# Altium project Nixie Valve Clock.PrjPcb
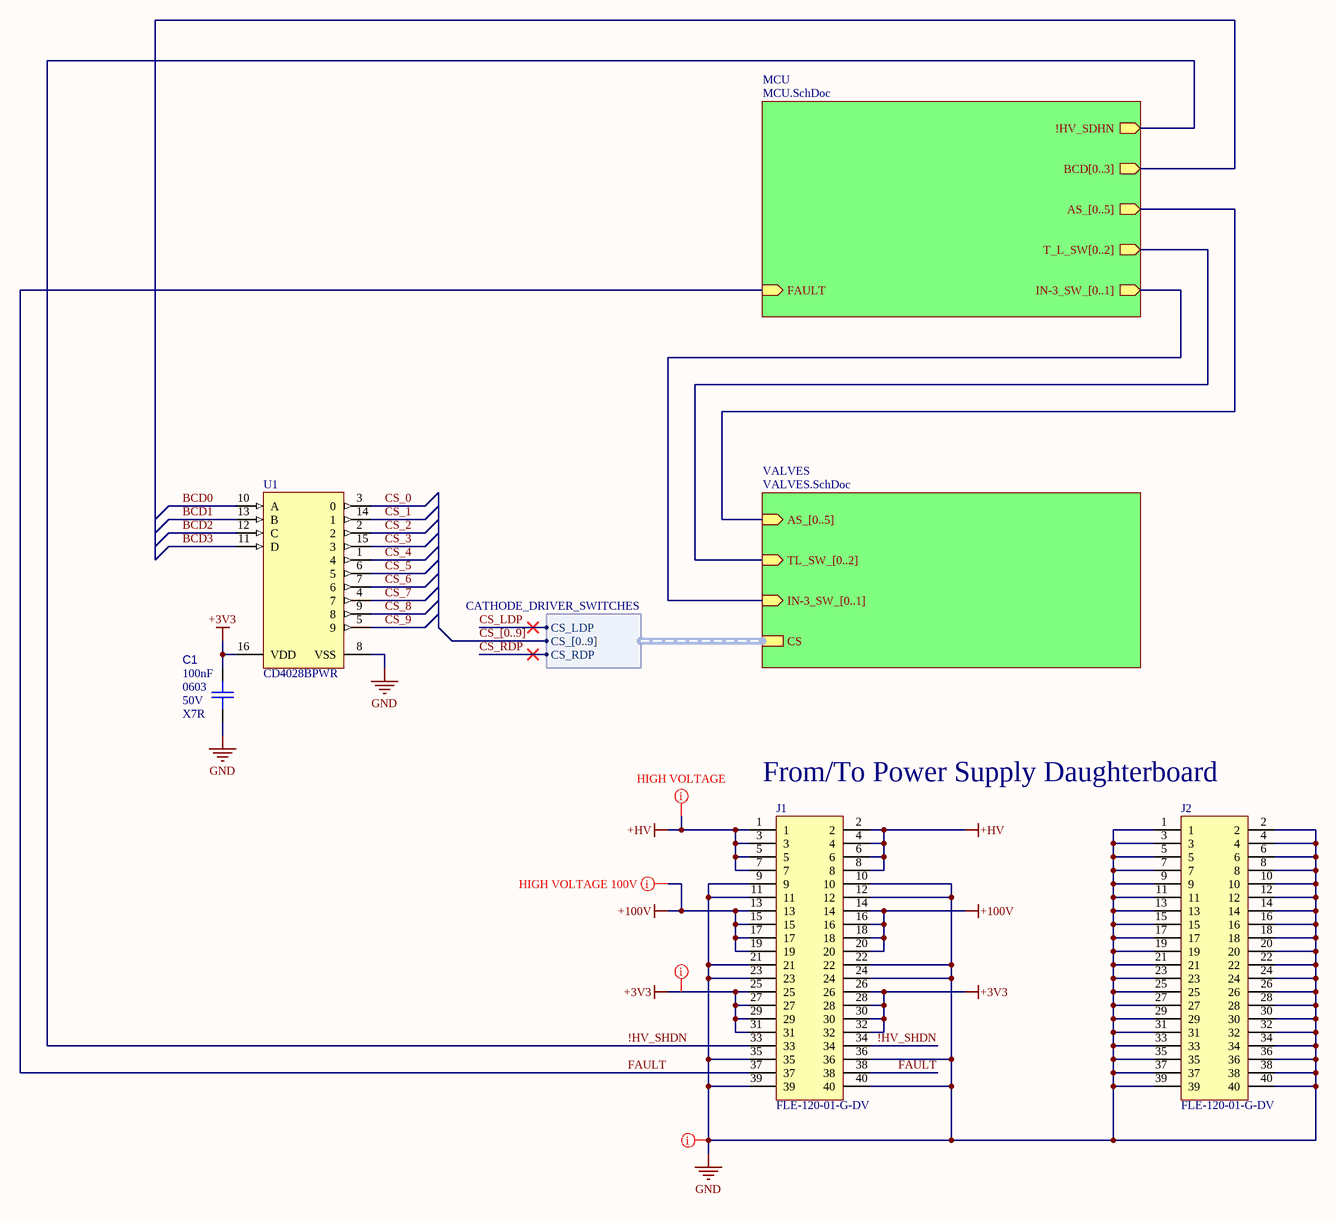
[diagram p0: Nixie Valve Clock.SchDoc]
9 sheets, 163 parts. Net scope: hierarchical (ports join the sheet entries above them; power ports are global).
Board file: Nixie Valve Clock.PcbDoc
Sheets:
  Nixie Valve Clock.SchDoc
    MCU = MCU.SchDoc
    VALVES = VALVES.SchDoc
      IN-14 VALVE ANODE DRIVER0 = IN-14 VALVE ANODE DRIVER.SchDoc
      IN-14 VALVE ANODE DRIVER1 = IN-14 VALVE ANODE DRIVER.SchDoc
      IN-14 VALVE ANODE DRIVER2 = IN-14 VALVE ANODE DRIVER.SchDoc
      IN-14 VALVE ANODE DRIVER3 = IN-14 VALVE ANODE DRIVER.SchDoc
      IN-14 VALVE ANODE DRIVER4 = IN-14 VALVE ANODE DRIVER.SchDoc
      IN-14 VALVE ANODE DRIVER5 = IN-14 VALVE ANODE DRIVER.SchDoc
      IN-14 VALVE CATHODE DRIVER_0 = IN-14 VALVE CATHODE DRIVER.SchDoc
      IN-14 VALVE CATHODE DRIVER_1 = IN-14 VALVE CATHODE DRIVER.SchDoc
      IN-14 VALVE CATHODE DRIVER_2 = IN-14 VALVE CATHODE DRIVER.SchDoc
      IN-14 VALVE CATHODE DRIVER_3 = IN-14 VALVE CATHODE DRIVER.SchDoc
      IN-14 VALVE CATHODE DRIVER_4 = IN-14 VALVE CATHODE DRIVER.SchDoc
      IN-14 VALVE CATHODE DRIVER_5 = IN-14 VALVE CATHODE DRIVER.SchDoc
      IN-14 VALVE CATHODE DRIVER_6 = IN-14 VALVE CATHODE DRIVER.SchDoc
      IN-14 VALVE CATHODE DRIVER_7 = IN-14 VALVE CATHODE DRIVER.SchDoc
      IN-14 VALVE CATHODE DRIVER_8 = IN-14 VALVE CATHODE DRIVER.SchDoc
      IN-14 VALVE CATHODE DRIVER_9 = IN-14 VALVE CATHODE DRIVER.SchDoc
      IN-14_VALVE_x2_0 = IN-14 VALVE x2.SchDoc
        IN-14 VALVE_0 = IN-14 VALVE.SchDoc
        IN-14 VALVE_1 = IN-14 VALVE.SchDoc
      IN-14_VALVE_x2_1 = IN-14 VALVE x2.SchDoc
        IN-14 VALVE_0 = IN-14 VALVE.SchDoc
        IN-14 VALVE_1 = IN-14 VALVE.SchDoc
      IN-14_VALVE_x2_2 = IN-14 VALVE x2.SchDoc
        IN-14 VALVE_0 = IN-14 VALVE.SchDoc
        IN-14 VALVE_1 = IN-14 VALVE.SchDoc
      IN-3 VALVE_0 = IN-3 VALVE.SchDoc
      IN-3 VALVE_1 = IN-3 VALVE.SchDoc
      IN-3 VALVE CATHODE DRIVER0 = IN-3 VALVE CATHODE DRIVER.SchDoc
      IN-3 VALVE CATHODE DRIVER1 = IN-3 VALVE CATHODE DRIVER.SchDoc

## Sheet Nixie Valve Clock.SchDoc
size A3; SheetNumber: 1; SheetTotal: 9

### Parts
(Parts that share a designator on the sheet are numbered #1, #2 ... from top to bottom, then left to right.)
?#1  (no value)
C1  value 100nF  Voltage Rating: 50V  Case/Package: 0603  Dielectric: X7R  [CAPC1608X09N]  (hidden comment: CGA3E2X7R1H104K080AA)
J1  FLE-120-01-G-DV  [FLE-120-01-XX-DV]
J2  FLE-120-01-G-DV  [FLE-120-01-XX-DV]
U1  CD4028BPWR  [PW0016A_N]

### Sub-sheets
MCU = MCU.SchDoc: AS_[0..5] (out), BCD[0..3] (out), T_L_SW[0..2] (out), IN-3_SW_[0..1] (out), !HV_SDHN (out), FAULT (in)
VALVES = VALVES.SchDoc: AS_[0..5] (in), CS (harness CATHODE_DRIVER_SWITCHES), TL_SW_[0..2] (in), IN-3_SW_[0..1] (in)

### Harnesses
CATHODE_DRIVER_SWITCHES: CS_LDP, CS_[0..9], CS_RDP

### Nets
+3V3: C1.1 J1.25 J1.26 J1.27 J1.28 J1.29 J1.30 J1.31 J1.32 U1.16(VDD)
+100V: J1.13 J1.14 J1.15 J1.16 J1.17 J1.18 J1.19 J1.20
+HV: J1.1 J1.2 J1.3 J1.4 J1.5 J1.6 J1.7 J1.8
GND: C1.2 J1.9 J1.10 J1.11 J1.12 J1.21 J1.22 J1.23 J1.24 J1.35 J1.36 J1.39 J1.40 J2.1 J2.2 J2.3 J2.4 J2.5 J2.6 J2.7 J2.8 J2.9 J2.10 J2.11 J2.12 J2.13 J2.14 J2.15 J2.16 J2.17 J2.18 J2.19 J2.20 J2.21 J2.22 J2.23 J2.24 J2.25 J2.26 J2.27 J2.28 J2.29 J2.30 J2.31 J2.32 J2.33 J2.34 J2.35 J2.36 J2.37 J2.38 J2.39 J2.40 U1.8(VSS)
!HV_SHDN: J1.33 J1.34 ; sheet MCU/!HV_SDHN
BCD0: U1.10(A)
BCD1: U1.13(B)
BCD2: U1.12(C)
BCD3: U1.11(D)
CS_0: U1.3(0)
CS_1: U1.14(1)
CS_2: U1.2
CS_3: U1.15(3)
CS_4: U1.1(4)
CS_5: U1.6(5)
CS_6: U1.7(6)
CS_7: U1.4(7)
CS_8: U1.9(8)
CS_9: U1.5(9)
FAULT: J1.37 J1.38 ; sheet MCU/FAULT

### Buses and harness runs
bus CS_[0..9]
bus sheet MCU/AS_[0..5] = sheet VALVES/AS_[0..5]
bus sheet MCU/IN-3_SW_[0..1] = sheet VALVES/IN-3_SW_[0..1]
bus sheet MCU/T_L_SW[0..2] = sheet VALVES/TL_SW_[0..2]

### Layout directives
net class HIGH VOLTAGE: +HV
net class HIGH VOLTAGE 100V: +100V
net class POWER: +3V3, GND

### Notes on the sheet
- From/To Power Supply Daughterboard

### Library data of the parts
?#1 = CMP-00003-4: The KETS Schematic Sheet Title Block
C1 = CMP-001-00101-1: Ceramic Capacitor, Multilayer, Ceramic, 50V, 10% +Tol, 10% -Tol, X7R, 15% TC, 0.1uF, Surface Mount, 0603; Reference Standard: AEC-Q200; Multilayer: Yes
J1 J2 = CMP-073-000000-3: PCB Receptacle, Board-to-Board, Wire-to-Board, 1.27 mm, 2 Rows, 40 Contacts, Surface Mount; Manufacturer Lifecycle Status: PRODUCTION; Pitch: 1.27mm; MF: Samtec; Connector Type: Receptacle, Socket; Number of Contacts: 40; Max Current Rating: 1.75A; Contact Resistance: 15mΩ
U1 = CMP-00024-00008-1: CMOS BCD-to-Decimal or Binary-to-Octal Decoders/Drivers 16-TSSOP -55 to 125; Manufacturer Lifecycle Status: ACTIVE; Min Supply Voltage: 3V; Bandwidth: 8MHz; Number of Outputs: 10; Propagation Delay: 160ns; Logic Function: Decoder, Demultiplexer; Number of Elements: 1; Turn-On Delay Time: 350ns; Polarity: Non-Inverting; Max Supply Voltage: 18V; Number of Inputs: 4; Low Level Output Current: 6.8mA; Quiescent Current: 100µA; Supply Type: Dual, Single

## Sheet MCU.SchDoc
size A3; SheetNumber: 2; SheetTotal: 9
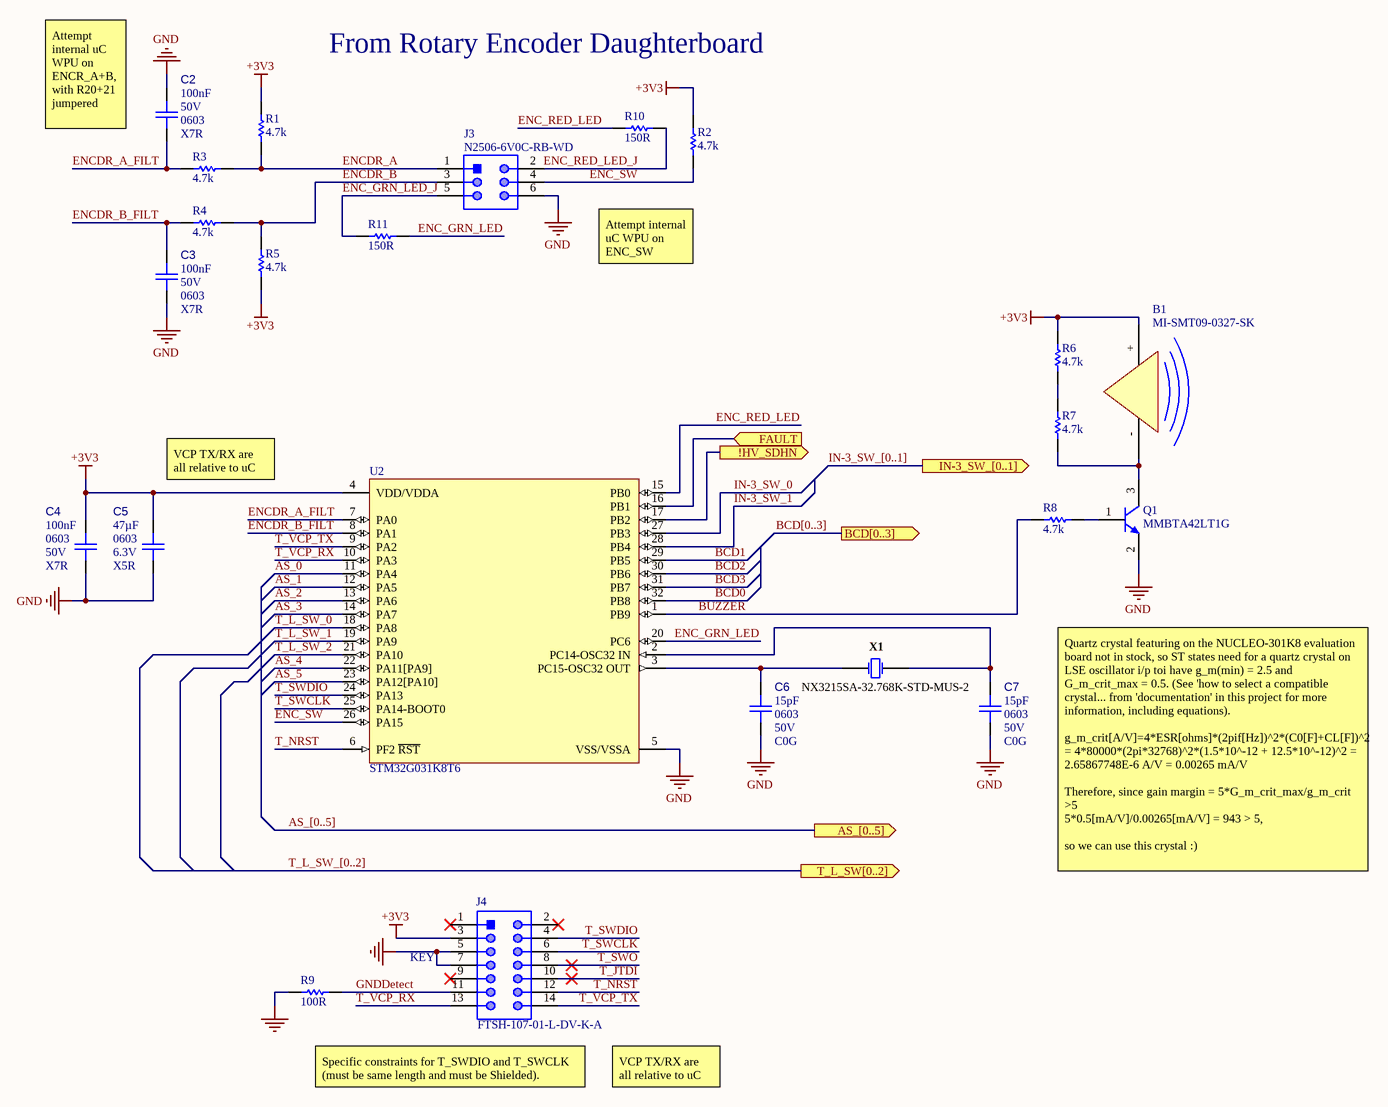
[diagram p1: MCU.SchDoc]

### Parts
(Parts that share a designator on the sheet are numbered #1, #2 ... from top to bottom, then left to right.)
?#2  (no value)
B1  MI-SMT09-0327-SK  [INDP9696X53N]
C2  value 100nF  Voltage Rating: 50V  Case/Package: 0603  Dielectric: X7R  [CAPC1608X09N]  (hidden comment: CGA3E2X7R1H104K080AA)
C3  value 100nF  Voltage Rating: 50V  Case/Package: 0603  Dielectric: X7R  [CAPC1608X09N]  (hidden comment: CGA3E2X7R1H104K080AA)
C4  value 100nF  Voltage Rating: 50V  Case/Package: 0603  Dielectric: X7R  [CAPC1608X09N]  (hidden comment: CGA3E2X7R1H104K080AA)
C5  value 47µF  Dielectric: X5R  Voltage Rating: 6.3V  Case/Package: 0603  [CAPC1608X87X35NL15T15]  (hidden comment: 06036D476MAT2A)
C6  value 15pF  Voltage Rating: 50V  Dielectric: C0G  Case/Package: 0603  [CAPC1608X87X35NL15T15]  (hidden comment: C0603X150J5GACTU)
C7  value 15pF  Voltage Rating: 50V  Dielectric: C0G  Case/Package: 0603  [CAPC1608X87X35NL15T15]  (hidden comment: C0603X150J5GACTU)
J3  N2506-6V0C-RB-WD  [N2506-6V0C-RB-WD-Footprint-1]
J4  FTSH-107-01-L-DV-K-A  [FP-FTSH-107-01-L-DV-K-A-MFG]
Q1  MMBTA42LT1G  [ONSC-SOT-23-3-318-08_V]
R1  value 4.7k  [RESC1608X55X25NL10T15]  (hidden comment: Resistor 4k7 +/-1% 0603 100 mW)
R2  value 4.7k  [RESC1608X55X25NL10T15]  (hidden comment: Resistor 4k7 +/-1% 0603 100 mW)
R3  value 4.7k  [RESC1608X55X25NL10T15]  (hidden comment: Resistor 4k7 +/-1% 0603 100 mW)
R4  value 4.7k  [RESC1608X55X25NL10T15]  (hidden comment: Resistor 4k7 +/-1% 0603 100 mW)
R5  value 4.7k  [RESC1608X55X25NL10T15]  (hidden comment: Resistor 4k7 +/-1% 0603 100 mW)
R6  value 4.7k  [RESC1608X55X25NL10T15]  (hidden comment: Resistor 4k7 +/-1% 0603 100 mW)
R7  value 4.7k  [RESC1608X55X25NL10T15]  (hidden comment: Resistor 4k7 +/-1% 0603 100 mW)
R8  value 4.7k  [RESC1608X55X25NL10T15]  (hidden comment: Resistor 4k7 +/-1% 0603 100 mW)
R9  value 100R  [RESC1608X55X25NL10T15]  (hidden comment: ERJ-3EKF1000V)
R10  value 150R  [RESC1608X55X25NL10T15]  (hidden comment: CRCW0603150RFKEAHP)
R11  value 150R  [RESC1608X55X25NL10T15]  (hidden comment: CRCW0603150RFKEAHP)
U2  STM32G031K8T6  [TQFP80P900X900X160-32N]
X1  NX3215SA-32.768K-STD-MUS-2  [NX3215SA-32.768K-STD-MUS-2-Footprint-1]

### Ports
!HV_SDHN (out), AS_[0..5] (out), BCD[0..3] (out), FAULT (in), IN-3_SW_[0..1] (out), T_L_SW[0..2] (out)

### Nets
+3V3: B1.+(VCC) C4.1 C5.1 J4.3 R1.2 R2.2 R5.1 R6.2 U2.4(VDD/VDDA)
GND: C2.2 C3.1 C4.2 C5.2 C6.2 C7.2 J3.6 J4.5 J4.7 Q1.2(E) R9.1 U2.5(VSS/VSSA)
!HV_SHDN: U2.17(PB2) ; port !HV_SDHN
AS_0: U2.11(PA4)
AS_1: U2.12(PA5)
AS_2: U2.13(PA6)
AS_3: U2.14(PA7)
AS_4: U2.22(PA11[PA9])
AS_5: U2.23(PA12[PA10])
BCD0: U2.32(PB8)
BCD1: U2.29(PB5)
BCD2: U2.30(PB6)
BCD3: U2.31(PB7)
BUZZER: R8.1 U2.1(PB9)
ENC_GRN_LED: R11.2 U2.20(PC6)
ENC_GRN_LED_J: J3.5 R11.1
ENC_RED_LED: R10.2 U2.15(PB0)
ENC_RED_LED_J: J3.2 R10.1
ENC_SW: J3.4 R2.1 U2.26(PA15)
ENCDR_A: J3.1 R1.1 R3.2
ENCDR_A_FILT: C2.1 R3.1 U2.7(PA0)
ENCDR_B: J3.3 R4.2 R5.2
ENCDR_B_FILT: C3.2 R4.1 U2.8(PA1)
FAULT: U2.16(PB1) ; port FAULT
GNDDetect: J4.11 R9.2
IN-3_SW_0: U2.27(PB3)
IN-3_SW_1: U2.28(PB4)
T_JTDI: J4.10
T_L_SW_0: U2.18(PA8)
T_L_SW_1: U2.19(PA9)
T_L_SW_2: U2.21(PA10)
T_NRST: J4.12 U2.6(PF2_~{RST})
T_SWCLK: J4.6 U2.25(PA14-BOOT0)
T_SWDIO: J4.4 U2.24(PA13)
T_SWO: J4.8
T_VCP_RX: J4.13 U2.10(PA3)
T_VCP_TX: J4.14 U2.9(PA2)
NetB1_-: B1.-(GND) Q1.3(C) R7.1
NetC6_1: C6.1 U2.3(PC15-OSC32_OUT) X1.1
NetC7_1: C7.1 U2.2(PC14-OSC32_IN) X1.2
NetQ1_1: Q1.1(B) R8.2
NetR6_1: R6.1 R7.2

Not connected (* = marked no-connect by the designer): J4 1* 2* 9*

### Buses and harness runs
bus AS_[0..5] = port AS_[0..5]
bus BCD[0..3] = port BCD[0..3]
bus IN-3_SW_[0..1] = port IN-3_SW_[0..1]
bus T_L_SW_[0..2] = port T_L_SW[0..2]

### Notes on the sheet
- From Rotary Encoder Daughterboard
- (near C2) Attempt internal uC WPU on ENCR_A+B, with R20+21 jumpered
- Attempt internal uC WPU on ENC_SW
- VCP TX/RX are all relative to uC
- Quartz crystal featuring on the NUCLEO-301K8 evaluation board not in stock, so ST states need for a quartz crystal on LSE oscillator i/p toi have g_m(min) = 2.5 and G_m_crit_max = 0.5. (See 'how to select a compatible crystal... from 'documentation' in this project for more information, including equations).
  g_m_crit[A/V]=4*ESR[ohms]*(2pif[Hz])^2*(C0[F]+CL[F])^2 = 4*80000*(2pi*32768)^2*(1.5*10^-12 + 12.5*10^-12)^2 = 2.65867748E-6 A/V = 0.00265 mA/V
  Therefore, since gain margin = 5*G_m_crit_max/g_m_crit >5
  5*0.5[mA/V]/0.00265[mA/V] = 943 > 5,
  so we can use this crystal :)
- (near J4) KEY
- Specific constraints for T_SWDIO and T_SWCLK (must be same length and must be Shielded).

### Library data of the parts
?#2 = CMP-00003-4: The KETS Schematic Sheet Title Block
B1 = CMP-00030-00004-2: Magnetic Indicator SMT 9.6MM 3V
C2-C4 = CMP-001-00101-1: as C1 on sheet Nixie Valve Clock
C5 = CMP-00388-1: 0603 (1608Metric) CERAMIC CAPACITOR ceramic capacitor 6.3V 47uF ±20% X5R; Capacitor Type: MLCC
C6 C7 = CMP-00385-1: Cap Ceramic 15pF 50V C0G 5% Pad SMD 0603 Flexible Termination 125C Extreme Low ESR T/R
J3 = CMP-002-00208-1: 80001386988 N2506-6V0C-Rb-Wd=06//Ht/Vsmt/30U/Rohs/Cap/T&r; Number of Positions: 6; Current Rating: 5A; Pitch: 2.54mm; Connector Type: Male Pin; Insulation Resistance: 1GΩ; Plating Thickness: 762nm; Row Spacing: 6.86mm
J4 = CMP-002-00203-1: Conn Unshrouded Header HDR 14 POS 1.27mm Solder ST Top Entry SMD TIGER CLAW™ Tube; Manufacturer Lifecycle Status: PRODUCTION; Current Rating: 3.4A; Gender: Male; Number of Contacts: 14
Q1 = CMP-013-00062-1: Bipolar (BJT) Single Transistor, General Purpose, NPN, 300 V, 500 mA, 225 mW, SOT-23, Surface Mount; Manufacturer Lifecycle Status: ACTIVE; Frequency: 50MHz; Max Collector Current: 500mA; Collector Emitter Breakdown Voltage: 300V; Emitter Base Voltage (VEBO): 6V; Collector Emitter Saturation Voltage: 500mV; Number of Elements: 1; Max Power Dissipation: 300mW; hFE Min: 40
R1-R8 = CMP-009-00031-13: Chip Resistor, 4.7 KOhm, +/- 1%, 0.1 W, -55 to 155 degC, 0603 (1608 Metric); Power: 100mW
R9 = CMP-00265-1: Fixed Resistor, Metal Glaze/thick Film, 0.1W, 100ohm, 75V, 1% +/-Tol, 100ppm/Cel, Surface Mount, 0603; Package Length: 1.6mm; Package Height: 0.45mm; Power: 100mW; Temperature Coefficient (ppm/Cel): 100; Package Width: 0.8mm; Reference Standard: AEC-Q200; Rated Temperature: 70°C
R10 R11 = CMP-00382-2: Res Thick Film 0603 150 Ohm 1% 1/3W ±100ppm/°C Molded SMD SMD Paper T/R; Voltage Rating: 75V; Power Rating: 330mW; Max Power Dissipation: 250mW; Power: 100mW
U2 = CMP-00383-2: RISC Microcontroller, 32-Bit, FLASH, CORTEX-M0 CPU, 64MHz, CMOS, PQFP32; Supply Voltage Max: 3.6V; Min Supply Voltage: 1.7V; Flash Memory Size: 64kB; EEPROM Memory Size: 0B; Number of A/D Converters: 1; Clock Frequency: 48MHz; Number of USART Channels: 2; Data Memory: 8K; Program Memory: 64K; Peripherals: POR; RAM Size: 8kB; Number of I/Os: 3; Operating Supply Voltage: 1.8V; ADC Channels (Resolution): 16-Ch 12-Bit; Number of Timers/Counters: 9; Number of PWM Channels: 17; Max Junction Temperature (Tj): 105°C; Data Bus Width: 32b; Register Bit Depth: 32; Max Supply Current: 6.9mA; Core Architecture: ARM Cortex-M0+; Interface: I2C, I2S, IrDA, LIN, SMBus, SPI, UART, USART; Number of ADC Channels: 16
X1 = CMP-003-00032-2: Crystal 0.032768MHz ±20ppm (Tol) 12.5pF FUND 80000Ohm Automotive AEC-Q200 2-Pin SMD; ESR (Equivalent Series Resistance): 80kΩ; ESR: 80k; Frequency Tolerance: 0.002%; Frequency: 32.768kHz; Frequency Stability: 400ppm

## Sheet VALVES.SchDoc
size A3; SheetNumber: 3; SheetTotal: 9
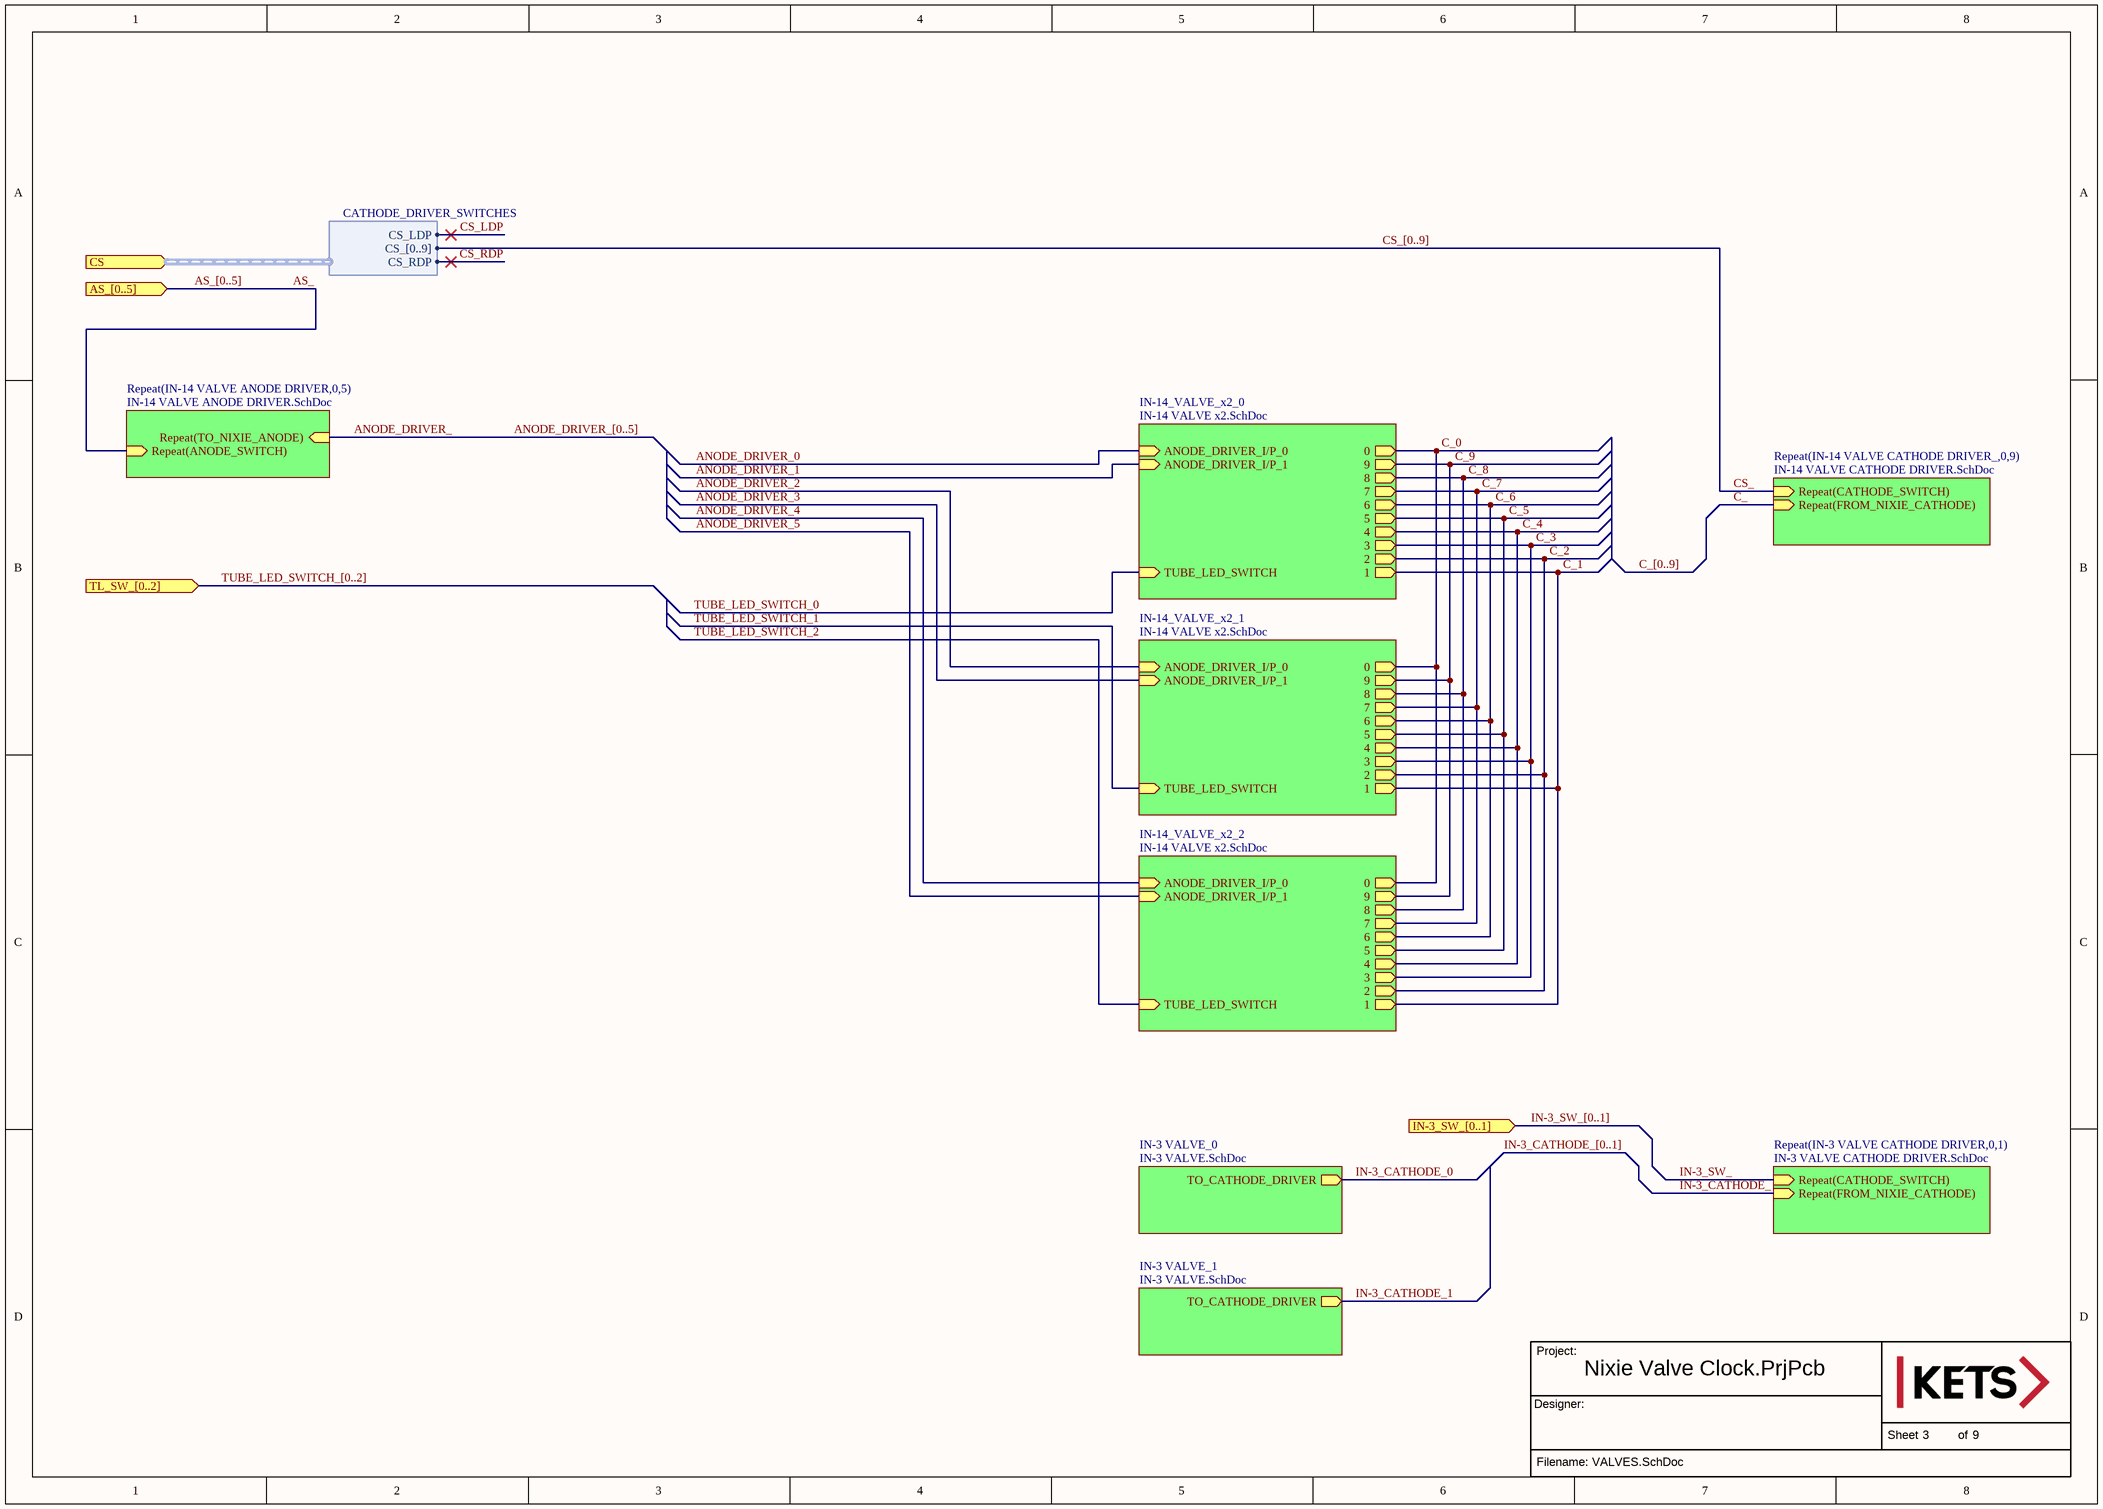
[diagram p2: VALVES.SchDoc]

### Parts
(Parts that share a designator on the sheet are numbered #1, #2 ... from top to bottom, then left to right.)
?#3  (no value)

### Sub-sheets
IN-3 VALVE_0 = IN-3 VALVE.SchDoc: TO_CATHODE_DRIVER (out)
IN-3 VALVE_1 = IN-3 VALVE.SchDoc: TO_CATHODE_DRIVER (out)
IN-14_VALVE_x2_0 = IN-14 VALVE x2.SchDoc: ANODE_DRIVER_I/P_0 (in), ANODE_DRIVER_I/P_1 (in), TUBE_LED_SWITCH (in), 0 (out), 9 (out), 8 (out), 7 (out), 6 (out), 5 (out), 4 (out), 3 (out), 2 (out), 1 (out)
IN-14_VALVE_x2_1 = IN-14 VALVE x2.SchDoc: ANODE_DRIVER_I/P_0 (in), ANODE_DRIVER_I/P_1 (in), TUBE_LED_SWITCH (in), 0 (out), 9 (out), 8 (out), 7 (out), 6 (out), 5 (out), 4 (out), 3 (out), 2 (out), 1 (out)
IN-14_VALVE_x2_2 = IN-14 VALVE x2.SchDoc: ANODE_DRIVER_I/P_0 (in), ANODE_DRIVER_I/P_1 (in), TUBE_LED_SWITCH (in), 0 (out), 9 (out), 8 (out), 7 (out), 6 (out), 5 (out), 4 (out), 3 (out), 2 (out), 1 (out)
Repeat(IN-3 VALVE CATHODE DRIVER,0,1) = IN-3 VALVE CATHODE DRIVER.SchDoc: Repeat(CATHODE_SWITCH) (in), Repeat(FROM_NIXIE_CATHODE) (in)
Repeat(IN-14 VALVE ANODE DRIVER,0,5) = IN-14 VALVE ANODE DRIVER.SchDoc: Repeat(ANODE_SWITCH) (in), Repeat(TO_NIXIE_ANODE) (in)
Repeat(IN-14 VALVE CATHODE DRIVER_,0,9) = IN-14 VALVE CATHODE DRIVER.SchDoc: Repeat(CATHODE_SWITCH) (in), Repeat(FROM_NIXIE_CATHODE) (in)

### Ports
AS_[0..5] (in), CS (in, harness CATHODE_DRIVER_SWITCHES), IN-3_SW_[0..1] (in), TL_SW_[0..2] (in)

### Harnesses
CATHODE_DRIVER_SWITCHES: CS_LDP, CS_[0..9], CS_RDP

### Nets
C_0: sheet IN-14_VALVE_x2_0/0, sheet IN-14_VALVE_x2_1/0, sheet IN-14_VALVE_x2_2/0
C_1: sheet IN-14_VALVE_x2_0/1, sheet IN-14_VALVE_x2_1/1, sheet IN-14_VALVE_x2_2/1
C_2: sheet IN-14_VALVE_x2_0/2, sheet IN-14_VALVE_x2_1/2, sheet IN-14_VALVE_x2_2/2
C_3: sheet IN-14_VALVE_x2_0/3, sheet IN-14_VALVE_x2_1/3, sheet IN-14_VALVE_x2_2/3
C_4: sheet IN-14_VALVE_x2_0/4, sheet IN-14_VALVE_x2_1/4, sheet IN-14_VALVE_x2_2/4
C_5: sheet IN-14_VALVE_x2_0/5, sheet IN-14_VALVE_x2_1/5, sheet IN-14_VALVE_x2_2/5
C_6: sheet IN-14_VALVE_x2_0/6, sheet IN-14_VALVE_x2_1/6, sheet IN-14_VALVE_x2_2/6
C_7: sheet IN-14_VALVE_x2_0/7, sheet IN-14_VALVE_x2_1/7, sheet IN-14_VALVE_x2_2/7
C_8: sheet IN-14_VALVE_x2_0/8, sheet IN-14_VALVE_x2_1/8, sheet IN-14_VALVE_x2_2/8
C_9: sheet IN-14_VALVE_x2_0/9, sheet IN-14_VALVE_x2_1/9, sheet IN-14_VALVE_x2_2/9

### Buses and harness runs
bus ANODE_DRIVER_[0..5]
bus AS_[0..5] = port AS_[0..5]
bus C_[0..9]
bus CS_[0..9]
bus IN-3_CATHODE_[0..1]
bus IN-3_SW_[0..1] = port IN-3_SW_[0..1]
bus TUBE_LED_SWITCH_[0..2] = port TL_SW_[0..2]

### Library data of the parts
?#3 = CMP-00003-4: The KETS Schematic Sheet Title Block

## Sheet IN-14 VALVE ANODE DRIVER.SchDoc
size A4; SheetNumber: 6; SheetTotal: 9
Used 6 times, as channels VALVES/IN-14 VALVE ANODE DRIVER0, VALVES/IN-14 VALVE ANODE DRIVER1, VALVES/IN-14 VALVE ANODE DRIVER2, VALVES/IN-14 VALVE ANODE DRIVER3, VALVES/IN-14 VALVE ANODE DRIVER4, VALVES/IN-14 VALVE ANODE DRIVER5. Parts and nets are listed once, with the designators drawn on the sheet.
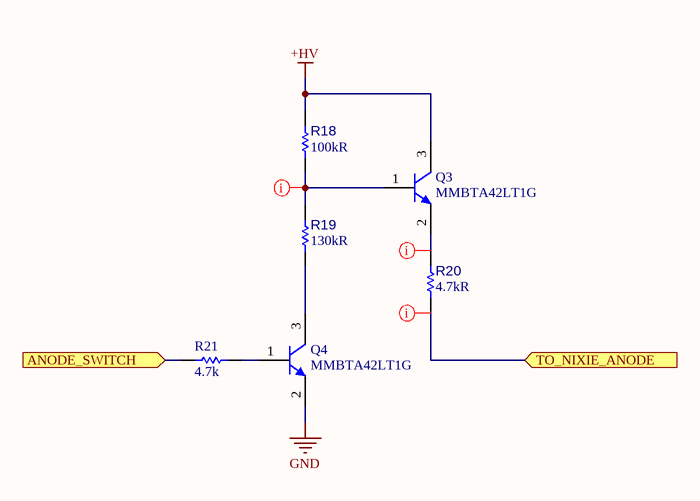
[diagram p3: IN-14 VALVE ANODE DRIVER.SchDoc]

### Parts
?  (no value)
Q3  MMBTA42LT1G  [ONSC-SOT-23-3-318-08_V]
Q4  MMBTA42LT1G  [ONSC-SOT-23-3-318-08_V]
R18  value 100kR  [RESC3126X65X50NL10T20]  (hidden comment: CRGCQ1210F100K)
R19  value 130kR  [RESC3126X65X50NL10T20]  (hidden comment: ERJP14F1303U)
R20  value 4.7kR  [RESC3126X65X50NL10T20]  (hidden comment: CRGCQ1210F4K7)
R21  value 4.7k  [RESC1608X55X25NL10T15]  (hidden comment: Resistor 4k7 +/-1% 0603 100 mW)

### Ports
ANODE_SWITCH (in), TO_NIXIE_ANODE (in)

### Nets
+HV: Q3.3(C) R18.2
GND: Q4.2(E)
ANODE_SWITCH: R21.1 ; port ANODE_SWITCH
TO_NIXIE_ANODE: R20.1 ; port TO_NIXIE_ANODE
NetQ3_1: Q3.1(B) R18.1 R19.2
NetQ3_2: Q3.2(E) R20.2
NetQ4_1: Q4.1(B) R21.2
NetQ4_3: Q4.3(C) R19.1

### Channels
VALVES/IN-14 VALVE ANODE DRIVER0: designators end in A; ports ANODE_SWITCH=AS_0 TO_NIXIE_ANODE=ANODE_DRIVER_0
VALVES/IN-14 VALVE ANODE DRIVER1: designators end in B; ports ANODE_SWITCH=AS_1 TO_NIXIE_ANODE=ANODE_DRIVER_1
VALVES/IN-14 VALVE ANODE DRIVER2: designators end in C; ports ANODE_SWITCH=AS_2 TO_NIXIE_ANODE=ANODE_DRIVER_2
VALVES/IN-14 VALVE ANODE DRIVER3: designators end in D; ports ANODE_SWITCH=AS_3 TO_NIXIE_ANODE=ANODE_DRIVER_3
VALVES/IN-14 VALVE ANODE DRIVER4: designators end in E; ports ANODE_SWITCH=AS_4 TO_NIXIE_ANODE=ANODE_DRIVER_4
VALVES/IN-14 VALVE ANODE DRIVER5: designators end in F; ports ANODE_SWITCH=AS_5 TO_NIXIE_ANODE=ANODE_DRIVER_5

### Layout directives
net class HIGH VOLTAGE: ANODE_DRIVER_0, NetQ3A_1, NetQ3A_2

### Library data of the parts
? = CMP-00003-4: The KETS Schematic Sheet Title Block
Q3 Q4 = CMP-013-00062-1: as Q1 on sheet MCU
R18 = CMP-00394-2: Res Thick Film 1210 100K Ohm 1% 0.5W(1/2W) ±100ppm/C Pad SMD Automotive T/R; Manufacturer Lifecycle Status: ACTIVE; Working Voltage: 200V; Power: 500mW; Temperature Coefficient: 100ppm/°C
R19 = CMP-00392-1: Res Thick Film 1210 130K Ohm 1% 0.5W ±100ppm/°C Molded SMD Embossed Carrier T/R; Manufacturer Lifecycle Status: ACTIVE; Part Series: Anti-Surge High Power Thick Film Chip Resistors; Power Rating: 500mW; Working Voltage: 200V
R20 = CMP-00386-2: Res Thick Film 1210 4.7K Ohm 1% 0.5W(1/2W) ±100ppm/C Pad SMD T/R Automotive AEC-Q200; Manufacturer Lifecycle Status: ACTIVE; Voltage Rating (DC): 200V; Temperature Coefficient: 100ppm/°C; Power Dissipation: 500mW
R21 = CMP-009-00031-13: as R1 on sheet MCU

## Sheet IN-14 VALVE CATHODE DRIVER.SchDoc
size A4; SheetNumber: 7; SheetTotal: 9
Used 10 times, as channels VALVES/IN-14 VALVE CATHODE DRIVER_0, VALVES/IN-14 VALVE CATHODE DRIVER_1, VALVES/IN-14 VALVE CATHODE DRIVER_2, VALVES/IN-14 VALVE CATHODE DRIVER_3, VALVES/IN-14 VALVE CATHODE DRIVER_4, VALVES/IN-14 VALVE CATHODE DRIVER_5, VALVES/IN-14 VALVE CATHODE DRIVER_6, VALVES/IN-14 VALVE CATHODE DRIVER_7, VALVES/IN-14 VALVE CATHODE DRIVER_8, VALVES/IN-14 VALVE CATHODE DRIVER_9. Parts and nets are listed once, with the designators drawn on the sheet.
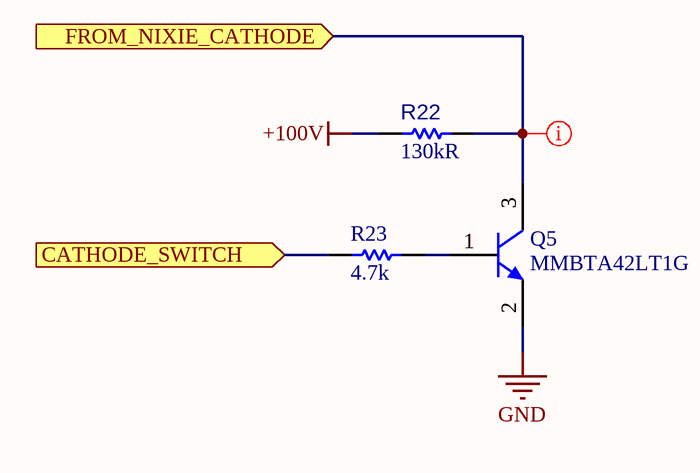
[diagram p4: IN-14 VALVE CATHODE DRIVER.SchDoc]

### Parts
?  (no value)
Q5  MMBTA42LT1G  [ONSC-SOT-23-3-318-08_V]
R22  value 130kR  [RESC3126X65X50NL10T20]  (hidden comment: ERJP14F1303U)
R23  value 4.7k  [RESC1608X55X25NL10T15]  (hidden comment: Resistor 4k7 +/-1% 0603 100 mW)

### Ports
CATHODE_SWITCH (in), FROM_NIXIE_CATHODE (in)

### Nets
+100V: R22.2
GND: Q5.2(E)
CATHODE_SWITCH: R23.1 ; port CATHODE_SWITCH
FROM_NIXIE_CATHODE: Q5.3(C) R22.1 ; port FROM_NIXIE_CATHODE
NetQ5_1: Q5.1(B) R23.2

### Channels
VALVES/IN-14 VALVE CATHODE DRIVER_0: designators end in A; ports CATHODE_SWITCH=CS_0 FROM_NIXIE_CATHODE=C_0
VALVES/IN-14 VALVE CATHODE DRIVER_1: designators end in B; ports CATHODE_SWITCH=CS_1 FROM_NIXIE_CATHODE=C_1
VALVES/IN-14 VALVE CATHODE DRIVER_2: designators end in C; ports CATHODE_SWITCH=CS_2 FROM_NIXIE_CATHODE=C_2
VALVES/IN-14 VALVE CATHODE DRIVER_3: designators end in D; ports CATHODE_SWITCH=CS_3 FROM_NIXIE_CATHODE=C_3
VALVES/IN-14 VALVE CATHODE DRIVER_4: designators end in E; ports CATHODE_SWITCH=CS_4 FROM_NIXIE_CATHODE=C_4
VALVES/IN-14 VALVE CATHODE DRIVER_5: designators end in F; ports CATHODE_SWITCH=CS_5 FROM_NIXIE_CATHODE=C_5
VALVES/IN-14 VALVE CATHODE DRIVER_6: designators end in G; ports CATHODE_SWITCH=CS_6 FROM_NIXIE_CATHODE=C_6
VALVES/IN-14 VALVE CATHODE DRIVER_7: designators end in H; ports CATHODE_SWITCH=CS_7 FROM_NIXIE_CATHODE=C_7
VALVES/IN-14 VALVE CATHODE DRIVER_8: designators end in I; ports CATHODE_SWITCH=CS_8 FROM_NIXIE_CATHODE=C_8
VALVES/IN-14 VALVE CATHODE DRIVER_9: designators end in J; ports CATHODE_SWITCH=CS_9 FROM_NIXIE_CATHODE=C_9

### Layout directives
net class HIGH VOLTAGE 100V: C_0

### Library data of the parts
? = CMP-00003-4: The KETS Schematic Sheet Title Block
Q5 = CMP-013-00062-1: as Q1 on sheet MCU
R22 = CMP-00392-1: as R19 on sheet IN-14 VALVE ANODE DRIVER
R23 = CMP-009-00031-13: as R1 on sheet MCU

## Sheet IN-14 VALVE x2.SchDoc
size A4; SheetNumber: 4; SheetTotal: 9
Used 3 times, as channels VALVES/IN-14_VALVE_x2_0, VALVES/IN-14_VALVE_x2_1, VALVES/IN-14_VALVE_x2_2. Parts and nets are listed once, with the designators drawn on the sheet.
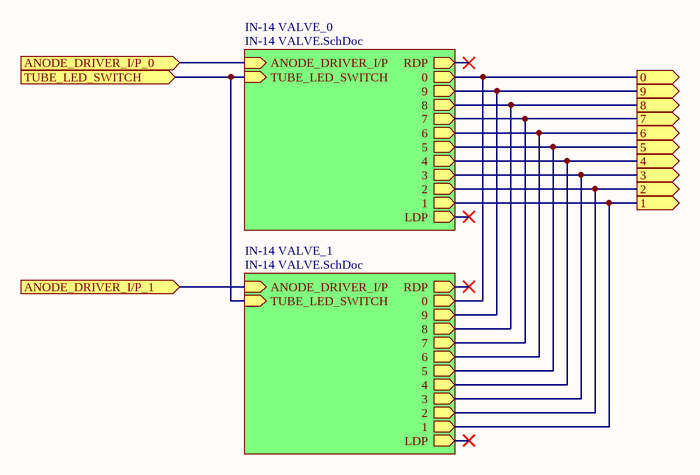
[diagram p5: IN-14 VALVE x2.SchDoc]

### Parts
?  (no value)

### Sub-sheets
IN-14 VALVE_0 = IN-14 VALVE.SchDoc: ANODE_DRIVER_I/P (in), RDP (out), 0 (out), 9 (out), 8 (out), 7 (out), 6 (out), 5 (out), 4 (out), 3 (out), 2 (out), 1 (out), LDP (out), TUBE_LED_SWITCH (in)
IN-14 VALVE_1 = IN-14 VALVE.SchDoc: ANODE_DRIVER_I/P (in), RDP (out), 0 (out), 9 (out), 8 (out), 7 (out), 6 (out), 5 (out), 4 (out), 3 (out), 2 (out), 1 (out), LDP (out), TUBE_LED_SWITCH (in)

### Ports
0 (out), 1 (out), 2 (out), 3 (out), 4 (out), 5 (out), 6 (out), 7 (out), 8 (out), 9 (out), ANODE_DRIVER_I/P_0 (in), ANODE_DRIVER_I/P_1 (in), TUBE_LED_SWITCH (in)

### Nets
0: port 0, sheet IN-14 VALVE_0/0, sheet IN-14 VALVE_1/0
1: port 1, sheet IN-14 VALVE_0/1, sheet IN-14 VALVE_1/1
2: port 2, sheet IN-14 VALVE_0/2, sheet IN-14 VALVE_1/2
3: port 3, sheet IN-14 VALVE_0/3, sheet IN-14 VALVE_1/3
4: port 4, sheet IN-14 VALVE_0/4, sheet IN-14 VALVE_1/4
5: port 5, sheet IN-14 VALVE_0/5, sheet IN-14 VALVE_1/5
6: port 6, sheet IN-14 VALVE_0/6, sheet IN-14 VALVE_1/6
7: port 7, sheet IN-14 VALVE_0/7, sheet IN-14 VALVE_1/7
8: port 8, sheet IN-14 VALVE_0/8, sheet IN-14 VALVE_1/8
9: port 9, sheet IN-14 VALVE_0/9, sheet IN-14 VALVE_1/9
ANODE_DRIVER_I/P_0: port ANODE_DRIVER_I/P_0, sheet IN-14 VALVE_0/ANODE_DRIVER_I/P
ANODE_DRIVER_I/P_1: port ANODE_DRIVER_I/P_1, sheet IN-14 VALVE_1/ANODE_DRIVER_I/P
TUBE_LED_SWITCH: port TUBE_LED_SWITCH, sheet IN-14 VALVE_0/TUBE_LED_SWITCH, sheet IN-14 VALVE_1/TUBE_LED_SWITCH

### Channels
VALVES/IN-14_VALVE_x2_0: ports 0=C_0 1=C_1 2=C_2 3=C_3 4=C_4 5=C_5 6=C_6 7=C_7 8=C_8 9=C_9 ANODE_DRIVER_I/P_0=ANODE_DRIVER_0 ANODE_DRIVER_I/P_1=ANODE_DRIVER_1 TUBE_LED_SWITCH=T_L_SW_0
VALVES/IN-14_VALVE_x2_1: ports 0=C_0 1=C_1 2=C_2 3=C_3 4=C_4 5=C_5 6=C_6 7=C_7 8=C_8 9=C_9 ANODE_DRIVER_I/P_0=ANODE_DRIVER_2 ANODE_DRIVER_I/P_1=ANODE_DRIVER_3 TUBE_LED_SWITCH=T_L_SW_1
VALVES/IN-14_VALVE_x2_2: ports 0=C_0 1=C_1 2=C_2 3=C_3 4=C_4 5=C_5 6=C_6 7=C_7 8=C_8 9=C_9 ANODE_DRIVER_I/P_0=ANODE_DRIVER_4 ANODE_DRIVER_I/P_1=ANODE_DRIVER_5 TUBE_LED_SWITCH=T_L_SW_2

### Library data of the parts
? = CMP-00003-4: The KETS Schematic Sheet Title Block

## Sheet IN-14 VALVE.SchDoc
size A4; SheetNumber: 5; SheetTotal: 9
Used 6 times, as channels VALVES/IN-14_VALVE_x2_0/IN-14 VALVE_0, VALVES/IN-14_VALVE_x2_0/IN-14 VALVE_1, VALVES/IN-14_VALVE_x2_1/IN-14 VALVE_0, VALVES/IN-14_VALVE_x2_1/IN-14 VALVE_1, VALVES/IN-14_VALVE_x2_2/IN-14 VALVE_0, VALVES/IN-14_VALVE_x2_2/IN-14 VALVE_1. Parts and nets are listed once, with the designators drawn on the sheet.
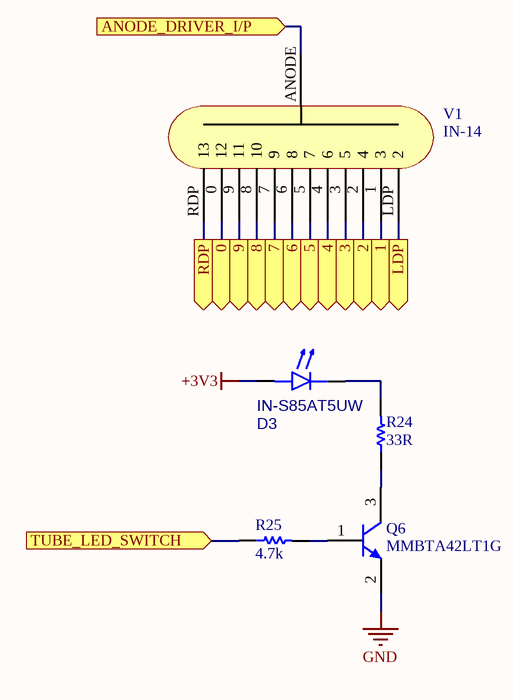
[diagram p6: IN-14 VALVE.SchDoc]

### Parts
?  (no value)
D3  IN-S85AT5UW  [DIOC2012X11N]
Q6  MMBTA42LT1G  [ONSC-SOT-23-3-318-08_V]
R24  value 33R  [RESC1608X55X25NL10T15]  (hidden comment: ERJ-3EKF33R0V)
R25  value 4.7k  [RESC1608X55X25NL10T15]  (hidden comment: Resistor 4k7 +/-1% 0603 100 mW)
V1  IN-14  [Nixie IN-14 Valve]

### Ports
0 (out), 1 (out), 2 (out), 3 (out), 4 (out), 5 (out), 6 (out), 7 (out), 8 (out), 9 (out), ANODE_DRIVER_I/P (in), LDP (out), RDP (out), TUBE_LED_SWITCH (in)

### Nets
+3V3: D3.2(A)
GND: Q6.2(E)
0: V1.0(12) ; port 0
1: V1.1(3) ; port 1
2: V1.2(4) ; port 2
3: V1.3(5) ; port 3
4: V1.4(6) ; port 4
5: V1.5(7) ; port 5
6: V1.6(8) ; port 6
7: V1.7(9) ; port 7
8: V1.8(10) ; port 8
9: V1.9(11) ; port 9
ANODE_DRIVER_I/P: V1.ANODE ; port ANODE_DRIVER_I/P
LDP: V1.LDP(2) ; port LDP
RDP: V1.RDP(13) ; port RDP
TUBE_LED_SWITCH: R25.1 ; port TUBE_LED_SWITCH
NetD3_1: D3.1(K) R24.2
NetQ6_1: Q6.1(B) R25.2
NetQ6_3: Q6.3(C) R24.1

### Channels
VALVES/IN-14_VALVE_x2_0/IN-14 VALVE_0: designators end in A; ports 0=C_0 1=C_1 2=C_2 3=C_3 4=C_4 5=C_5 6=C_6 7=C_7 8=C_8 9=C_9 ANODE_DRIVER_I/P=ANODE_DRIVER_0 LDP=LDP_IN-14 VALVE_0 RDP=RDP_IN-14 VALVE_0 TUBE_LED_SWITCH=T_L_SW_0
VALVES/IN-14_VALVE_x2_0/IN-14 VALVE_1: designators end in B; ports 0=C_0 1=C_1 2=C_2 3=C_3 4=C_4 5=C_5 6=C_6 7=C_7 8=C_8 9=C_9 ANODE_DRIVER_I/P=ANODE_DRIVER_1 LDP=LDP_IN-14 VALVE_1 RDP=RDP_IN-14 VALVE_1 TUBE_LED_SWITCH=T_L_SW_0
VALVES/IN-14_VALVE_x2_1/IN-14 VALVE_0: designators end in C; ports 0=C_0 1=C_1 2=C_2 3=C_3 4=C_4 5=C_5 6=C_6 7=C_7 8=C_8 9=C_9 ANODE_DRIVER_I/P=ANODE_DRIVER_2 LDP=LDP_IN-14 VALVE_0 RDP=RDP_IN-14 VALVE_0 TUBE_LED_SWITCH=T_L_SW_1
VALVES/IN-14_VALVE_x2_1/IN-14 VALVE_1: designators end in D; ports 0=C_0 1=C_1 2=C_2 3=C_3 4=C_4 5=C_5 6=C_6 7=C_7 8=C_8 9=C_9 ANODE_DRIVER_I/P=ANODE_DRIVER_3 LDP=LDP_IN-14 VALVE_1 RDP=RDP_IN-14 VALVE_1 TUBE_LED_SWITCH=T_L_SW_1
VALVES/IN-14_VALVE_x2_2/IN-14 VALVE_0: designators end in E; ports 0=C_0 1=C_1 2=C_2 3=C_3 4=C_4 5=C_5 6=C_6 7=C_7 8=C_8 9=C_9 ANODE_DRIVER_I/P=ANODE_DRIVER_4 LDP=LDP_IN-14 VALVE_0 RDP=RDP_IN-14 VALVE_0 TUBE_LED_SWITCH=T_L_SW_2
VALVES/IN-14_VALVE_x2_2/IN-14 VALVE_1: designators end in F; ports 0=C_0 1=C_1 2=C_2 3=C_3 4=C_4 5=C_5 6=C_6 7=C_7 8=C_8 9=C_9 ANODE_DRIVER_I/P=ANODE_DRIVER_5 LDP=LDP_IN-14 VALVE_1 RDP=RDP_IN-14 VALVE_1 TUBE_LED_SWITCH=T_L_SW_2

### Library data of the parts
? = CMP-00003-4: The KETS Schematic Sheet Title Block
D3 = CMP-007-00039-1: SMD LED - Mono Color Top View, 805 1.1mm LED PCB Type, White, High Brightness, Clear Lens, Angle 120; Reverse Voltage: 5V; Nominal Vf: 3.4V; Number of Circuits: 1; Luminous Intensity: 285mcd; Forward Voltage: 2.8V; Forward Current: 25mA; Shape: Rectangular; Viewing Angle: 120°
Q6 = CMP-013-00062-1: as Q1 on sheet MCU
R24 = CMP-00050-3: Fixed Resistor, Metal Glaze/thick Film, 0.1W, 33ohm, 75V, 1% +/-Tol, 100ppm/Cel, Surface Mount, 0603; Package Width: 0.8mm; Package Height: 0.45mm; Rated Temperature: 70°C; Power: 100mW; Reference Standard: AEC-Q200; Package Length: 1.6mm; Temperature Coefficient: 100ppm/°C
R25 = CMP-009-00031-13: as R1 on sheet MCU
V1 = CMP-00026-00006-13: IN-14 Cold Cathode Valve

## Sheet IN-3 VALVE.SchDoc
size A4; SheetNumber: 8; SheetTotal: 9
Used 2 times, as channels VALVES/IN-3 VALVE_0, VALVES/IN-3 VALVE_1. Parts and nets are listed once, with the designators drawn on the sheet.
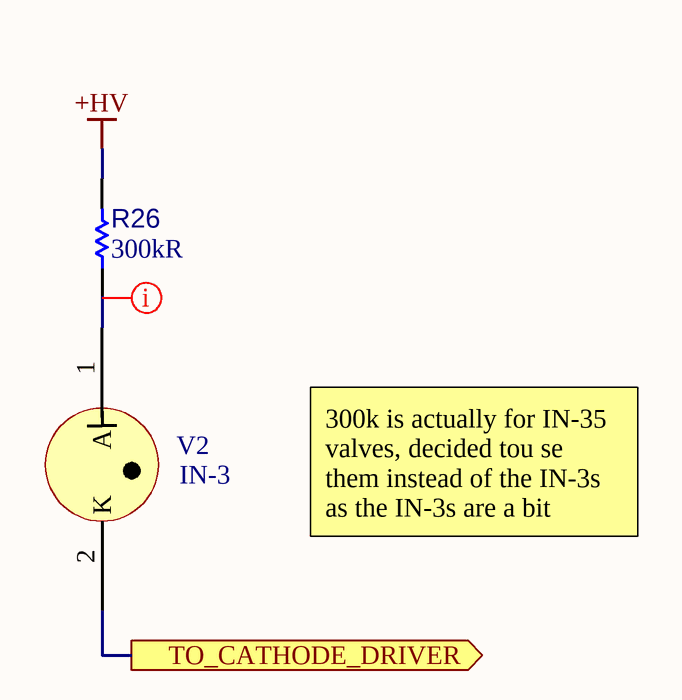
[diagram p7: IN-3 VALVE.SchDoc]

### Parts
?  (no value)
R26  value 300kR  [RESC3126X65X50NL10T20]  (hidden comment: SG73P2ETTD3003F)
V2  IN-3  [IN-3-Footprint-1]

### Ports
TO_CATHODE_DRIVER (out)

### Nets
+HV: R26.2
TO_CATHODE_DRIVER: V2.2(K) ; port TO_CATHODE_DRIVER
NetR26_1: R26.1 V2.1(A)

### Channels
VALVES/IN-3 VALVE_0: designators end in A; ports TO_CATHODE_DRIVER=IN-3_CATHODE_0
VALVES/IN-3 VALVE_1: designators end in B; ports TO_CATHODE_DRIVER=IN-3_CATHODE_1

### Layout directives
net class HIGH VOLTAGE: NetR26A_1

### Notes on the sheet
- 300k is actually for IN-35 valves, decided tou se them instead of the IN-3s as the IN-3s are a bit ugly(!)

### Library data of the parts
? = CMP-00003-4: The KETS Schematic Sheet Title Block
R26 = CMP-00405-2: Fixed Resistor, Metal Glaze/thick Film, 1.5W, 300000ohm, 200V, 1% +/-Tol, 200ppm/Cel, Surface Mount, 1210; Power Rating: 500mW; Temperature Coefficient: 200ppm/°C
V2 = CMP-00026-00007-7: IN-3 Cold Cathode Indicator Valve

## Sheet IN-3 VALVE CATHODE DRIVER.SchDoc
size A4; SheetNumber: 9; SheetTotal: 9
Used 2 times, as channels VALVES/IN-3 VALVE CATHODE DRIVER0, VALVES/IN-3 VALVE CATHODE DRIVER1. Parts and nets are listed once, with the designators drawn on the sheet.
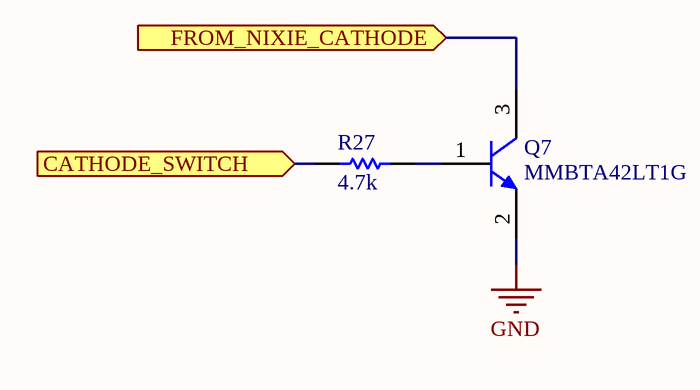
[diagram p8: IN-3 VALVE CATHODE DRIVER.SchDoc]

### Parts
?  (no value)
Q7  MMBTA42LT1G  [ONSC-SOT-23-3-318-08_V]
R27  value 4.7k  [RESC1608X55X25NL10T15]  (hidden comment: Resistor 4k7 +/-1% 0603 100 mW)

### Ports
CATHODE_SWITCH (in), FROM_NIXIE_CATHODE (in)

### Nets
GND: Q7.2(E)
CATHODE_SWITCH: R27.1 ; port CATHODE_SWITCH
FROM_NIXIE_CATHODE: Q7.3(C) ; port FROM_NIXIE_CATHODE
NetQ7_1: Q7.1(B) R27.2

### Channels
VALVES/IN-3 VALVE CATHODE DRIVER0: designators end in A; ports CATHODE_SWITCH=IN-3_SW_0 FROM_NIXIE_CATHODE=IN-3_CATHODE_0
VALVES/IN-3 VALVE CATHODE DRIVER1: designators end in B; ports CATHODE_SWITCH=IN-3_SW_1 FROM_NIXIE_CATHODE=IN-3_CATHODE_1

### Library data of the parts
? = CMP-00003-4: The KETS Schematic Sheet Title Block
Q7 = CMP-013-00062-1: as Q1 on sheet MCU
R27 = CMP-009-00031-13: as R1 on sheet MCU

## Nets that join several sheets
+3V3: Nixie Valve Clock (10 pins), MCU (9 pins), VALVES/IN-14_VALVE_x2_0/IN-14 VALVE_0 (D3A.2), VALVES/IN-14_VALVE_x2_0/IN-14 VALVE_1 (D3B.2), VALVES/IN-14_VALVE_x2_1/IN-14 VALVE_0 (D3C.2), VALVES/IN-14_VALVE_x2_1/IN-14 VALVE_1 (D3D.2), VALVES/IN-14_VALVE_x2_2/IN-14 VALVE_0 (D3E.2), VALVES/IN-14_VALVE_x2_2/IN-14 VALVE_1 (D3F.2)
+100V: Nixie Valve Clock (8 pins), VALVES/IN-14 VALVE CATHODE DRIVER_0 (R22A.2), VALVES/IN-14 VALVE CATHODE DRIVER_1 (R22B.2), VALVES/IN-14 VALVE CATHODE DRIVER_2 (R22C.2), VALVES/IN-14 VALVE CATHODE DRIVER_3 (R22D.2), VALVES/IN-14 VALVE CATHODE DRIVER_4 (R22E.2), VALVES/IN-14 VALVE CATHODE DRIVER_5 (R22F.2), VALVES/IN-14 VALVE CATHODE DRIVER_6 (R22G.2), VALVES/IN-14 VALVE CATHODE DRIVER_7 (R22H.2), VALVES/IN-14 VALVE CATHODE DRIVER_8 (R22I.2), VALVES/IN-14 VALVE CATHODE DRIVER_9 (R22J.2)
+HV: Nixie Valve Clock (8 pins), VALVES/IN-14 VALVE ANODE DRIVER0 (Q3A.3 R18A.2), VALVES/IN-14 VALVE ANODE DRIVER1 (Q3B.3 R18B.2), VALVES/IN-14 VALVE ANODE DRIVER2 (Q3C.3 R18C.2), VALVES/IN-14 VALVE ANODE DRIVER3 (Q3D.3 R18D.2), VALVES/IN-14 VALVE ANODE DRIVER4 (Q3E.3 R18E.2), VALVES/IN-14 VALVE ANODE DRIVER5 (Q3F.3 R18F.2), VALVES/IN-3 VALVE_0 (R26A.2), VALVES/IN-3 VALVE_1 (R26B.2)
GND: Nixie Valve Clock (54 pins), MCU (12 pins), VALVES/IN-14 VALVE ANODE DRIVER0 (Q4A.2), VALVES/IN-14 VALVE ANODE DRIVER1 (Q4B.2), VALVES/IN-14 VALVE ANODE DRIVER2 (Q4C.2), VALVES/IN-14 VALVE ANODE DRIVER3 (Q4D.2), VALVES/IN-14 VALVE ANODE DRIVER4 (Q4E.2), VALVES/IN-14 VALVE ANODE DRIVER5 (Q4F.2), VALVES/IN-14 VALVE CATHODE DRIVER_0 (Q5A.2), VALVES/IN-14 VALVE CATHODE DRIVER_1 (Q5B.2), VALVES/IN-14 VALVE CATHODE DRIVER_2 (Q5C.2), VALVES/IN-14 VALVE CATHODE DRIVER_3 (Q5D.2), VALVES/IN-14 VALVE CATHODE DRIVER_4 (Q5E.2), VALVES/IN-14 VALVE CATHODE DRIVER_5 (Q5F.2), VALVES/IN-14 VALVE CATHODE DRIVER_6 (Q5G.2), VALVES/IN-14 VALVE CATHODE DRIVER_7 (Q5H.2), VALVES/IN-14 VALVE CATHODE DRIVER_8 (Q5I.2), VALVES/IN-14 VALVE CATHODE DRIVER_9 (Q5J.2), VALVES/IN-14_VALVE_x2_0/IN-14 VALVE_0 (Q6A.2), VALVES/IN-14_VALVE_x2_0/IN-14 VALVE_1 (Q6B.2), VALVES/IN-14_VALVE_x2_1/IN-14 VALVE_0 (Q6C.2), VALVES/IN-14_VALVE_x2_1/IN-14 VALVE_1 (Q6D.2), VALVES/IN-14_VALVE_x2_2/IN-14 VALVE_0 (Q6E.2), VALVES/IN-14_VALVE_x2_2/IN-14 VALVE_1 (Q6F.2), VALVES/IN-3 VALVE CATHODE DRIVER0 (Q7A.2), VALVES/IN-3 VALVE CATHODE DRIVER1 (Q7B.2)
!HV_SHDN: Nixie Valve Clock (J1.33 J1.34), MCU (U2.17)
ANODE_DRIVER_0: VALVES/IN-14 VALVE ANODE DRIVER0 (R20A.1), VALVES/IN-14_VALVE_x2_0/IN-14 VALVE_0 (V1A.ANODE)
ANODE_DRIVER_1: VALVES/IN-14 VALVE ANODE DRIVER1 (R20B.1), VALVES/IN-14_VALVE_x2_0/IN-14 VALVE_1 (V1B.ANODE)
ANODE_DRIVER_2: VALVES/IN-14 VALVE ANODE DRIVER2 (R20C.1), VALVES/IN-14_VALVE_x2_1/IN-14 VALVE_0 (V1C.ANODE)
ANODE_DRIVER_3: VALVES/IN-14 VALVE ANODE DRIVER3 (R20D.1), VALVES/IN-14_VALVE_x2_1/IN-14 VALVE_1 (V1D.ANODE)
ANODE_DRIVER_4: VALVES/IN-14 VALVE ANODE DRIVER4 (R20E.1), VALVES/IN-14_VALVE_x2_2/IN-14 VALVE_0 (V1E.ANODE)
ANODE_DRIVER_5: VALVES/IN-14 VALVE ANODE DRIVER5 (R20F.1), VALVES/IN-14_VALVE_x2_2/IN-14 VALVE_1 (V1F.ANODE)
AS_0: MCU (U2.11), VALVES/IN-14 VALVE ANODE DRIVER0 (R21A.1)
AS_1: MCU (U2.12), VALVES/IN-14 VALVE ANODE DRIVER1 (R21B.1)
AS_2: MCU (U2.13), VALVES/IN-14 VALVE ANODE DRIVER2 (R21C.1)
AS_3: MCU (U2.14), VALVES/IN-14 VALVE ANODE DRIVER3 (R21D.1)
AS_4: MCU (U2.22), VALVES/IN-14 VALVE ANODE DRIVER4 (R21E.1)
AS_5: MCU (U2.23), VALVES/IN-14 VALVE ANODE DRIVER5 (R21F.1)
C_0: VALVES/IN-14 VALVE CATHODE DRIVER_0 (Q5A.3 R22A.1), VALVES/IN-14_VALVE_x2_0/IN-14 VALVE_0 (V1A.0), VALVES/IN-14_VALVE_x2_0/IN-14 VALVE_1 (V1B.0), VALVES/IN-14_VALVE_x2_1/IN-14 VALVE_0 (V1C.0), VALVES/IN-14_VALVE_x2_1/IN-14 VALVE_1 (V1D.0), VALVES/IN-14_VALVE_x2_2/IN-14 VALVE_0 (V1E.0), VALVES/IN-14_VALVE_x2_2/IN-14 VALVE_1 (V1F.0)
C_1: VALVES/IN-14 VALVE CATHODE DRIVER_1 (Q5B.3 R22B.1), VALVES/IN-14_VALVE_x2_0/IN-14 VALVE_0 (V1A.1), VALVES/IN-14_VALVE_x2_0/IN-14 VALVE_1 (V1B.1), VALVES/IN-14_VALVE_x2_1/IN-14 VALVE_0 (V1C.1), VALVES/IN-14_VALVE_x2_1/IN-14 VALVE_1 (V1D.1), VALVES/IN-14_VALVE_x2_2/IN-14 VALVE_0 (V1E.1), VALVES/IN-14_VALVE_x2_2/IN-14 VALVE_1 (V1F.1)
C_2: VALVES/IN-14 VALVE CATHODE DRIVER_2 (Q5C.3 R22C.1), VALVES/IN-14_VALVE_x2_0/IN-14 VALVE_0 (V1A.2), VALVES/IN-14_VALVE_x2_0/IN-14 VALVE_1 (V1B.2), VALVES/IN-14_VALVE_x2_1/IN-14 VALVE_0 (V1C.2), VALVES/IN-14_VALVE_x2_1/IN-14 VALVE_1 (V1D.2), VALVES/IN-14_VALVE_x2_2/IN-14 VALVE_0 (V1E.2), VALVES/IN-14_VALVE_x2_2/IN-14 VALVE_1 (V1F.2)
C_3: VALVES/IN-14 VALVE CATHODE DRIVER_3 (Q5D.3 R22D.1), VALVES/IN-14_VALVE_x2_0/IN-14 VALVE_0 (V1A.3), VALVES/IN-14_VALVE_x2_0/IN-14 VALVE_1 (V1B.3), VALVES/IN-14_VALVE_x2_1/IN-14 VALVE_0 (V1C.3), VALVES/IN-14_VALVE_x2_1/IN-14 VALVE_1 (V1D.3), VALVES/IN-14_VALVE_x2_2/IN-14 VALVE_0 (V1E.3), VALVES/IN-14_VALVE_x2_2/IN-14 VALVE_1 (V1F.3)
C_4: VALVES/IN-14 VALVE CATHODE DRIVER_4 (Q5E.3 R22E.1), VALVES/IN-14_VALVE_x2_0/IN-14 VALVE_0 (V1A.4), VALVES/IN-14_VALVE_x2_0/IN-14 VALVE_1 (V1B.4), VALVES/IN-14_VALVE_x2_1/IN-14 VALVE_0 (V1C.4), VALVES/IN-14_VALVE_x2_1/IN-14 VALVE_1 (V1D.4), VALVES/IN-14_VALVE_x2_2/IN-14 VALVE_0 (V1E.4), VALVES/IN-14_VALVE_x2_2/IN-14 VALVE_1 (V1F.4)
C_5: VALVES/IN-14 VALVE CATHODE DRIVER_5 (Q5F.3 R22F.1), VALVES/IN-14_VALVE_x2_0/IN-14 VALVE_0 (V1A.5), VALVES/IN-14_VALVE_x2_0/IN-14 VALVE_1 (V1B.5), VALVES/IN-14_VALVE_x2_1/IN-14 VALVE_0 (V1C.5), VALVES/IN-14_VALVE_x2_1/IN-14 VALVE_1 (V1D.5), VALVES/IN-14_VALVE_x2_2/IN-14 VALVE_0 (V1E.5), VALVES/IN-14_VALVE_x2_2/IN-14 VALVE_1 (V1F.5)
C_6: VALVES/IN-14 VALVE CATHODE DRIVER_6 (Q5G.3 R22G.1), VALVES/IN-14_VALVE_x2_0/IN-14 VALVE_0 (V1A.6), VALVES/IN-14_VALVE_x2_0/IN-14 VALVE_1 (V1B.6), VALVES/IN-14_VALVE_x2_1/IN-14 VALVE_0 (V1C.6), VALVES/IN-14_VALVE_x2_1/IN-14 VALVE_1 (V1D.6), VALVES/IN-14_VALVE_x2_2/IN-14 VALVE_0 (V1E.6), VALVES/IN-14_VALVE_x2_2/IN-14 VALVE_1 (V1F.6)
C_7: VALVES/IN-14 VALVE CATHODE DRIVER_7 (Q5H.3 R22H.1), VALVES/IN-14_VALVE_x2_0/IN-14 VALVE_0 (V1A.7), VALVES/IN-14_VALVE_x2_0/IN-14 VALVE_1 (V1B.7), VALVES/IN-14_VALVE_x2_1/IN-14 VALVE_0 (V1C.7), VALVES/IN-14_VALVE_x2_1/IN-14 VALVE_1 (V1D.7), VALVES/IN-14_VALVE_x2_2/IN-14 VALVE_0 (V1E.7), VALVES/IN-14_VALVE_x2_2/IN-14 VALVE_1 (V1F.7)
C_8: VALVES/IN-14 VALVE CATHODE DRIVER_8 (Q5I.3 R22I.1), VALVES/IN-14_VALVE_x2_0/IN-14 VALVE_0 (V1A.8), VALVES/IN-14_VALVE_x2_0/IN-14 VALVE_1 (V1B.8), VALVES/IN-14_VALVE_x2_1/IN-14 VALVE_0 (V1C.8), VALVES/IN-14_VALVE_x2_1/IN-14 VALVE_1 (V1D.8), VALVES/IN-14_VALVE_x2_2/IN-14 VALVE_0 (V1E.8), VALVES/IN-14_VALVE_x2_2/IN-14 VALVE_1 (V1F.8)
C_9: VALVES/IN-14 VALVE CATHODE DRIVER_9 (Q5J.3 R22J.1), VALVES/IN-14_VALVE_x2_0/IN-14 VALVE_0 (V1A.9), VALVES/IN-14_VALVE_x2_0/IN-14 VALVE_1 (V1B.9), VALVES/IN-14_VALVE_x2_1/IN-14 VALVE_0 (V1C.9), VALVES/IN-14_VALVE_x2_1/IN-14 VALVE_1 (V1D.9), VALVES/IN-14_VALVE_x2_2/IN-14 VALVE_0 (V1E.9), VALVES/IN-14_VALVE_x2_2/IN-14 VALVE_1 (V1F.9)
CS_0: Nixie Valve Clock (U1.3), VALVES/IN-14 VALVE CATHODE DRIVER_0 (R23A.1)
CS_1: Nixie Valve Clock (U1.14), VALVES/IN-14 VALVE CATHODE DRIVER_1 (R23B.1)
CS_2: Nixie Valve Clock (U1.2), VALVES/IN-14 VALVE CATHODE DRIVER_2 (R23C.1)
CS_3: Nixie Valve Clock (U1.15), VALVES/IN-14 VALVE CATHODE DRIVER_3 (R23D.1)
CS_4: Nixie Valve Clock (U1.1), VALVES/IN-14 VALVE CATHODE DRIVER_4 (R23E.1)
CS_5: Nixie Valve Clock (U1.6), VALVES/IN-14 VALVE CATHODE DRIVER_5 (R23F.1)
CS_6: Nixie Valve Clock (U1.7), VALVES/IN-14 VALVE CATHODE DRIVER_6 (R23G.1)
CS_7: Nixie Valve Clock (U1.4), VALVES/IN-14 VALVE CATHODE DRIVER_7 (R23H.1)
CS_8: Nixie Valve Clock (U1.9), VALVES/IN-14 VALVE CATHODE DRIVER_8 (R23I.1)
CS_9: Nixie Valve Clock (U1.5), VALVES/IN-14 VALVE CATHODE DRIVER_9 (R23J.1)
FAULT: Nixie Valve Clock (J1.37 J1.38), MCU (U2.16)
IN-3_CATHODE_0: VALVES/IN-3 VALVE_0 (V2A.2), VALVES/IN-3 VALVE CATHODE DRIVER0 (Q7A.3)
IN-3_CATHODE_1: VALVES/IN-3 VALVE_1 (V2B.2), VALVES/IN-3 VALVE CATHODE DRIVER1 (Q7B.3)
IN-3_SW_0: MCU (U2.27), VALVES/IN-3 VALVE CATHODE DRIVER0 (R27A.1)
IN-3_SW_1: MCU (U2.28), VALVES/IN-3 VALVE CATHODE DRIVER1 (R27B.1)
T_L_SW_0: MCU (U2.18), VALVES/IN-14_VALVE_x2_0/IN-14 VALVE_0 (R25A.1), VALVES/IN-14_VALVE_x2_0/IN-14 VALVE_1 (R25B.1)
T_L_SW_1: MCU (U2.19), VALVES/IN-14_VALVE_x2_1/IN-14 VALVE_0 (R25C.1), VALVES/IN-14_VALVE_x2_1/IN-14 VALVE_1 (R25D.1)
T_L_SW_2: MCU (U2.21), VALVES/IN-14_VALVE_x2_2/IN-14 VALVE_0 (R25E.1), VALVES/IN-14_VALVE_x2_2/IN-14 VALVE_1 (R25F.1)

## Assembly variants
Various DNF Variant of Nixie Valve Clock: not fitted C? C? R? R? R? R? R? V1A V1B V1C V1D V1E V1F V2A V2B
